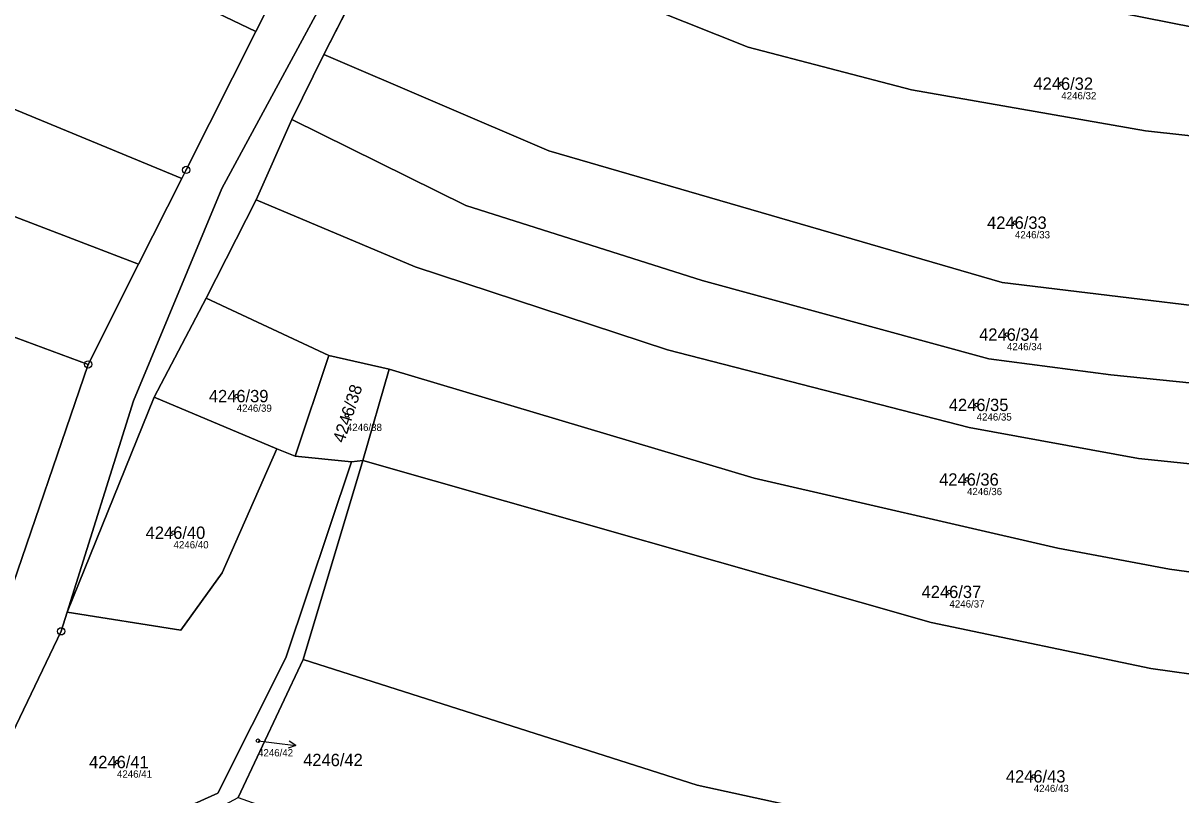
# Model space of a CAD drawing. Extents: x -739214 to -733252, y -1147612 to -1142842.
# Drawn here: x -737034.5 to -736874.9, y -1146662.3 to -1146556 of the extents above; entities that cross this region are included whole.
import ezdxf

# ---------------------------------------------------------------- set-up
doc = ezdxf.new("R2010")
doc.units = 0
for name, color, linetype in [('Definiční body', 7, 'Continuous'), ('Hranice parcel', 7, 'Continuous'), ('Parcelní čísla', 7, 'Continuous'), ('Polygon parcely', 7, 'Continuous'), ('Pop  PČ popisy', 7, 'Continuous'), ('Značky bodu BP', 7, 'Continuous')]:
    doc.layers.add(name, color=color, linetype=linetype)

msp = doc.modelspace()

# ---------------------------------------------------------------- linework, layer by layer
at = {"layer": 'Definiční body'}
for centre in [(-736891.39, -1146564.29), (-736897.78, -1146583.45), (-736898.88, -1146598.87), (-737005.07, -1146607.35), (-736903.06, -1146608.56), (-736989.88, -1146610), (-736904.39, -1146618.84), (-737013.78, -1146626.18), (-736906.81, -1146634.33), (-737002.13, -1146654.85), (-737021.58, -1146657.78), (-736895.19, -1146659.76)]:
    msp.add_circle(centre, 0.25, dxfattribs=at)
at = {"layer": 'Hranice parcel'}
for p, q in [((-736982.71, -1146540.04), (-736993.04, -1146560.27)), ((-736993.04, -1146560.27), (-736997.49, -1146569.21)), ((-736997.49, -1146569.21), (-737002.37, -1146580.32)), ((-737012.63, -1146577.36), (-737018.59, -1146589.18)), ((-737002.37, -1146580.32), (-737009.26, -1146593.87)), ((-737018.59, -1146589.18), (-737025.54, -1146602.98)), ((-737009.26, -1146593.87), (-737016.43, -1146607.5)), ((-737009.26, -1146593.87), (-736992.37, -1146601.76)), ((-736992.37, -1146601.76), (-736997.03, -1146615.65)), ((-736992.37, -1146601.76), (-736984.03, -1146603.65)), ((-736984.03, -1146603.65), (-736987.7, -1146616.21)), ((-737016.43, -1146607.5), (-737028.44, -1146637.14)), ((-737016.43, -1146607.5), (-736999.54, -1146614.61)), ((-736999.54, -1146614.61), (-736997.03, -1146615.65)), ((-736997.03, -1146615.65), (-736989.25, -1146616.43)), ((-736995.93, -1146643.63), (-736987.7, -1146616.21)), ((-736989.25, -1146616.43), (-736987.7, -1146616.21)), ((-737004.89, -1146662.68), (-736995.93, -1146643.63))]:
    msp.add_line(p, q, dxfattribs=at)
for points in [[(-736892.15, -1146372.58), (-736911.56, -1146401.33), (-736928.16, -1146428.6), (-736944.6, -1146461.03), (-736956.73, -1146488.03), (-736966, -1146508.44), (-736978.52, -1146528.94), (-736986.17, -1146539.99), (-737007.1, -1146578.74), (-737019.29, -1146608.02), (-737028.44, -1146637.14)], [(-737088.19, -1146522.47), (-737073.46, -1146528.51), (-737035.55, -1146541.22), (-737002.42, -1146557.08)], [(-736973.72, -1146526.93), (-736958.83, -1146533.93), (-736931.15, -1146543.94), (-736907.51, -1146549.7), (-736869.53, -1146557.25), (-736804.77, -1146566.35), (-736774.35, -1146571.16)], [(-737140.45, -1146530.12), (-737105.48, -1146542.82), (-737061.71, -1146557.08), (-737012.63, -1146577.36)], [(-736991, -1146534.58), (-737000.75, -1146553.75), (-737002.42, -1146557.08)], [(-736982.71, -1146540.04), (-736934.58, -1146559.27), (-736912.06, -1146565.15), (-736879.79, -1146570.8), (-736807.99, -1146578.69), (-736777.99, -1146584.35)], [(-737147.29, -1146545.75), (-737125.86, -1146554.68), (-737112.42, -1146558.69), (-737068.09, -1146570.2), (-737018.59, -1146589.18)], [(-737002.42, -1146557.08), (-737012.04, -1146576.18), (-737012.63, -1146577.36)], [(-736993.04, -1146560.27), (-736962.02, -1146573.56), (-736899.56, -1146591.68), (-736853.98, -1146597.23), (-736799.89, -1146602), (-736782.32, -1146605.12)], [(-737153.34, -1146561.58), (-737046.67, -1146595.19), (-737025.54, -1146602.98)], [(-736997.49, -1146569.21), (-736973.48, -1146581.1), (-736940.92, -1146591.44), (-736901.38, -1146602.22), (-736884.55, -1146604.43), (-736809.34, -1146612.11), (-736784.45, -1146615.33)], [(-737002.37, -1146580.32), (-736980.48, -1146589.55), (-736945.69, -1146600.99), (-736904.11, -1146611.7), (-736880.76, -1146615.97), (-736832.32, -1146620.97), (-736786.49, -1146625.1)], [(-737025.54, -1146602.98), (-737037.09, -1146636.71), (-737049.74, -1146664.12), (-737057.04, -1146673.42), (-737067.32, -1146683.11)], [(-736984.03, -1146603.65), (-736933.71, -1146618.65), (-736891.85, -1146628.32), (-736876.47, -1146631.19), (-736857.43, -1146633.83), (-736788.98, -1146640.27)], [(-737028.44, -1146637.14), (-737012.76, -1146639.62), (-737007.09, -1146631.73), (-736999.54, -1146614.61)], [(-737033.1, -1146672.19), (-737019.32, -1146667.3), (-737007.65, -1146662.08), (-736998.31, -1146643.4), (-736989.25, -1146616.43)], [(-736987.7, -1146616.21), (-736909.35, -1146638.55), (-736879.05, -1146644.89), (-736836.54, -1146650.87), (-736790.62, -1146655.79)], [(-737028.44, -1146637.14), (-737029.27, -1146639.77), (-737041.22, -1146664.59), (-737042.86, -1146667.48)], [(-736995.93, -1146643.63), (-736941.6, -1146660.97), (-736899.92, -1146670.08), (-736873.77, -1146674.75), (-736873.21, -1146671.3), (-736812.86, -1146676.97), (-736790.6, -1146676.25)]]:
    msp.add_lwpolyline(points, dxfattribs=at)
at = {"layer": 'Polygon parcely'}
for points in [[(-736966, -1146508.44), (-736978.52, -1146528.94), (-736986.17, -1146539.99), (-737007.1, -1146578.74), (-737019.29, -1146608.02), (-737028.44, -1146637.14), (-737016.43, -1146607.5), (-737009.26, -1146593.87), (-737002.37, -1146580.32), (-736997.49, -1146569.21), (-736993.04, -1146560.27), (-736982.71, -1146540.04), (-736973.72, -1146526.93), (-736966.05, -1146515.15), (-736961.72, -1146508.04), (-736943.5, -1146468.43), (-736934.95, -1146449.65), (-736929.07, -1146436.23), (-736907.67, -1146400.17), (-736892.15, -1146372.58), (-736911.56, -1146401.33), (-736928.16, -1146428.6), (-736944.6, -1146461.03), (-736956.73, -1146488.03)], [(-737105.48, -1146542.82), (-737061.71, -1146557.08), (-737012.63, -1146577.36), (-737012.04, -1146576.18), (-737002.42, -1146557.08), (-737035.55, -1146541.22), (-737073.46, -1146528.51), (-737088.19, -1146522.47), (-737118.67, -1146510.16), (-737135.37, -1146522.3), (-737140.45, -1146530.12)], [(-737035.55, -1146541.22), (-737002.42, -1146557.08), (-737000.75, -1146553.75), (-736991, -1146534.58), (-737015.23, -1146525), (-737046.88, -1146515.03), (-737077.25, -1146512.5), (-737088.19, -1146522.47), (-737073.46, -1146528.51)], [(-736804.77, -1146566.35), (-736774.35, -1146571.16), (-736770.76, -1146560.31), (-736768.92, -1146555.91), (-736790, -1146551.46), (-736822, -1146546.13), (-736838.67, -1146543.9), (-736892.37, -1146534.27), (-736897.26, -1146533.82), (-736928.71, -1146537.94), (-736937.49, -1146534.71), (-736941.04, -1146527.93), (-736943.6, -1146527.38), (-736966.05, -1146515.15), (-736973.72, -1146526.93), (-736958.83, -1146533.93), (-736931.15, -1146543.94), (-736907.51, -1146549.7), (-736869.53, -1146557.25)], [(-736934.58, -1146559.27), (-736912.06, -1146565.15), (-736879.79, -1146570.8), (-736807.99, -1146578.69), (-736777.99, -1146584.35), (-736776.76, -1146578.43), (-736774.35, -1146571.16), (-736804.77, -1146566.35), (-736869.53, -1146557.25), (-736907.51, -1146549.7), (-736931.15, -1146543.94), (-736958.83, -1146533.93), (-736973.72, -1146526.93), (-736982.71, -1146540.04)], [(-737068.09, -1146570.2), (-737018.59, -1146589.18), (-737012.63, -1146577.36), (-737061.71, -1146557.08), (-737105.48, -1146542.82), (-737140.45, -1146530.12), (-737147.29, -1146545.75), (-737125.86, -1146554.68), (-737112.42, -1146558.69)], [(-736962.02, -1146573.56), (-736899.56, -1146591.68), (-736853.98, -1146597.23), (-736799.89, -1146602), (-736782.32, -1146605.12), (-736777.99, -1146584.35), (-736807.99, -1146578.69), (-736879.79, -1146570.8), (-736912.06, -1146565.15), (-736934.58, -1146559.27), (-736982.71, -1146540.04), (-736993.04, -1146560.27)], [(-737147.29, -1146545.75), (-737153.34, -1146561.58), (-737046.67, -1146595.19), (-737025.54, -1146602.98), (-737018.59, -1146589.18), (-737068.09, -1146570.2), (-737112.42, -1146558.69), (-737125.86, -1146554.68)], [(-736884.55, -1146604.43), (-736809.34, -1146612.11), (-736784.45, -1146615.33), (-736782.32, -1146605.12), (-736799.89, -1146602), (-736853.98, -1146597.23), (-736899.56, -1146591.68), (-736962.02, -1146573.56), (-736993.04, -1146560.27), (-736997.49, -1146569.21), (-736973.48, -1146581.1), (-736940.92, -1146591.44), (-736901.38, -1146602.22)], [(-736786.49, -1146625.1), (-736784.45, -1146615.33), (-736809.34, -1146612.11), (-736884.55, -1146604.43), (-736901.38, -1146602.22), (-736940.92, -1146591.44), (-736973.48, -1146581.1), (-736997.49, -1146569.21), (-737002.37, -1146580.32), (-736980.48, -1146589.55), (-736945.69, -1146600.99), (-736904.11, -1146611.7), (-736880.76, -1146615.97), (-736832.32, -1146620.97)], [(-736933.71, -1146618.65), (-736891.85, -1146628.32), (-736876.47, -1146631.19), (-736857.43, -1146633.83), (-736788.98, -1146640.27), (-736786.49, -1146625.1), (-736832.32, -1146620.97), (-736880.76, -1146615.97), (-736904.11, -1146611.7), (-736945.69, -1146600.99), (-736980.48, -1146589.55), (-737002.37, -1146580.32), (-737009.26, -1146593.87), (-736992.37, -1146601.76), (-736984.03, -1146603.65)], [(-736999.54, -1146614.61), (-736997.03, -1146615.65), (-736992.37, -1146601.76), (-737009.26, -1146593.87), (-737016.43, -1146607.5)], [(-736997.03, -1146615.65), (-736989.25, -1146616.43), (-736987.7, -1146616.21), (-736984.03, -1146603.65), (-736992.37, -1146601.76)], [(-736790.62, -1146655.79), (-736789.82, -1146645.38), (-736788.98, -1146640.27), (-736857.43, -1146633.83), (-736876.47, -1146631.19), (-736891.85, -1146628.32), (-736933.71, -1146618.65), (-736984.03, -1146603.65), (-736987.7, -1146616.21), (-736909.35, -1146638.55), (-736879.05, -1146644.89), (-736836.54, -1146650.87)], [(-737028.44, -1146637.14), (-737012.76, -1146639.62), (-737007.09, -1146631.73), (-736999.54, -1146614.61), (-737016.43, -1146607.5)], [(-737019.32, -1146667.3), (-737007.65, -1146662.08), (-736998.31, -1146643.4), (-736989.25, -1146616.43), (-736997.03, -1146615.65), (-736999.54, -1146614.61), (-737007.09, -1146631.73), (-737012.76, -1146639.62), (-737028.44, -1146637.14), (-737029.27, -1146639.77), (-737041.22, -1146664.59), (-737042.86, -1146667.48), (-737033.1, -1146672.19)], [(-737004.89, -1146662.68), (-736995.93, -1146643.63), (-736987.7, -1146616.21), (-736989.25, -1146616.43), (-736998.31, -1146643.4), (-737007.65, -1146662.08), (-737019.32, -1146667.3), (-737033.1, -1146672.19), (-737030.43, -1146673.64), (-737017.39, -1146669.38)], [(-736873.21, -1146671.3), (-736812.86, -1146676.97), (-736790.6, -1146676.25), (-736791.57, -1146668.24), (-736790.62, -1146655.79), (-736836.54, -1146650.87), (-736879.05, -1146644.89), (-736909.35, -1146638.55), (-736987.7, -1146616.21), (-736995.93, -1146643.63), (-736941.6, -1146660.97), (-736899.92, -1146670.08), (-736873.77, -1146674.75)], [(-736967.21, -1146676.02), (-736939.93, -1146683.05), (-736916.69, -1146688.12), (-736884.18, -1146693.81), (-736829.71, -1146699.31), (-736803.29, -1146701.29), (-736783.02, -1146701.16), (-736789.65, -1146684.15), (-736790.6, -1146676.25), (-736812.86, -1146676.97), (-736873.21, -1146671.3), (-736873.77, -1146674.75), (-736899.92, -1146670.08), (-736941.6, -1146660.97), (-736995.93, -1146643.63), (-737004.89, -1146662.68), (-736974.86, -1146673.36)]]:
    msp.add_lwpolyline(points, close=True, dxfattribs=at)
for points in [[(-737141.72, -1146792), (-737109.21, -1146741.54), (-737108.87, -1146741.08), (-737102.79, -1146732.71), (-737094.09, -1146720.75), (-737093.68, -1146720.18), (-737082.85, -1146709.02), (-737076.22, -1146702.19), (-737068.74, -1146694.78), (-737052.19, -1146678.4), (-737050.66, -1146676.64), (-737046.12, -1146671.4), (-737043.08, -1146667.88), (-737042.86, -1146667.48), (-737041.22, -1146664.59), (-737029.27, -1146639.77), (-737028.44, -1146637.14), (-737019.29, -1146608.02), (-737007.1, -1146578.74), (-736986.17, -1146539.99)], [(-737000.75, -1146553.75), (-737002.42, -1146557.08), (-737012.04, -1146576.18), (-737012.63, -1146577.36), (-737018.59, -1146589.18), (-737025.54, -1146602.98), (-737037.09, -1146636.71), (-737049.74, -1146664.12), (-737057.04, -1146673.42), (-737067.32, -1146683.11), (-737082.07, -1146697.03), (-737097.8, -1146715.9), (-737105.99, -1146728.03), (-737113.33, -1146738.92), (-737121.17, -1146751.43)], [(-737131.38, -1146657.84), (-737105.78, -1146665.46), (-737088.98, -1146671.72), (-737067.32, -1146683.11), (-737057.04, -1146673.42), (-737049.74, -1146664.12), (-737037.09, -1146636.71), (-737025.54, -1146602.98), (-737046.67, -1146595.19), (-737153.34, -1146561.58)]]:
    msp.add_lwpolyline(points, dxfattribs=at)
at = {"layer": 'Pop  PČ popisy'}
for p, q in [((-737002.13, -1146654.85), (-736999.89, -1146655.14)), ((-736996.91, -1146655.51), (-736997.84, -1146654.89)), ((-736999.89, -1146655.14), (-736996.91, -1146655.51)), ((-736996.91, -1146655.51), (-736997.97, -1146655.88))]:
    msp.add_line(p, q, dxfattribs=at)
at = {"layer": 'Značky bodu BP'}
for centre, radius in [((-737012.04, -1146576.18), 0.5), ((-737012.04, -1146576.18), 0.0303), ((-737025.54, -1146602.98), 0.5), ((-737025.54, -1146602.98), 0.0303), ((-737029.27, -1146639.77), 0.5), ((-737029.27, -1146639.77), 0.0303)]:
    msp.add_circle(centre, radius, dxfattribs=at)

# ---------------------------------------------------------------- texts
at = {"layer": 'Definiční body'}
for s, p in [('4246/32', (-736891.39, -1146566.45)), ('4246/33', (-736897.78, -1146585.61)), ('4246/34', (-736898.88, -1146601.03)), ('4246/39', (-737005.07, -1146609.51)), ('4246/35', (-736903.06, -1146610.72)), ('4246/38', (-736989.88, -1146612.16)), ('4246/36', (-736904.39, -1146621)), ('4246/40', (-737013.78, -1146628.34)), ('4246/37', (-736906.81, -1146636.49)), ('4246/42', (-737002.13, -1146657.01)), ('4246/41', (-737021.58, -1146659.94)), ('4246/43', (-736895.19, -1146661.92))]:
    msp.add_text(s, height=1, dxfattribs=at).set_placement(p)
at = {"layer": 'Parcelní čísla'}
for s, p in [('4246/32', (-736895.23, -1146565.14)), ('4246/33', (-736901.62, -1146584.3)), ('4246/34', (-736902.72, -1146599.72)), ('4246/39', (-737008.91, -1146608.2)), ('4246/35', (-736906.9, -1146609.41)), ('4246/36', (-736908.23, -1146619.69)), ('4246/40', (-737017.62, -1146627.03)), ('4246/37', (-736910.65, -1146635.18)), ('4246/42', (-736995.91, -1146658.35)), ('4246/41', (-737025.42, -1146658.63)), ('4246/43', (-736899.03, -1146660.61))]:
    msp.add_text(s, height=1.7, dxfattribs=at).set_placement(p)
msp.add_text('4246/38', height=1.7, rotation=72, dxfattribs=at).set_placement((-736990.26, -1146613.91))

doc.saveas('drawing.dxf')
